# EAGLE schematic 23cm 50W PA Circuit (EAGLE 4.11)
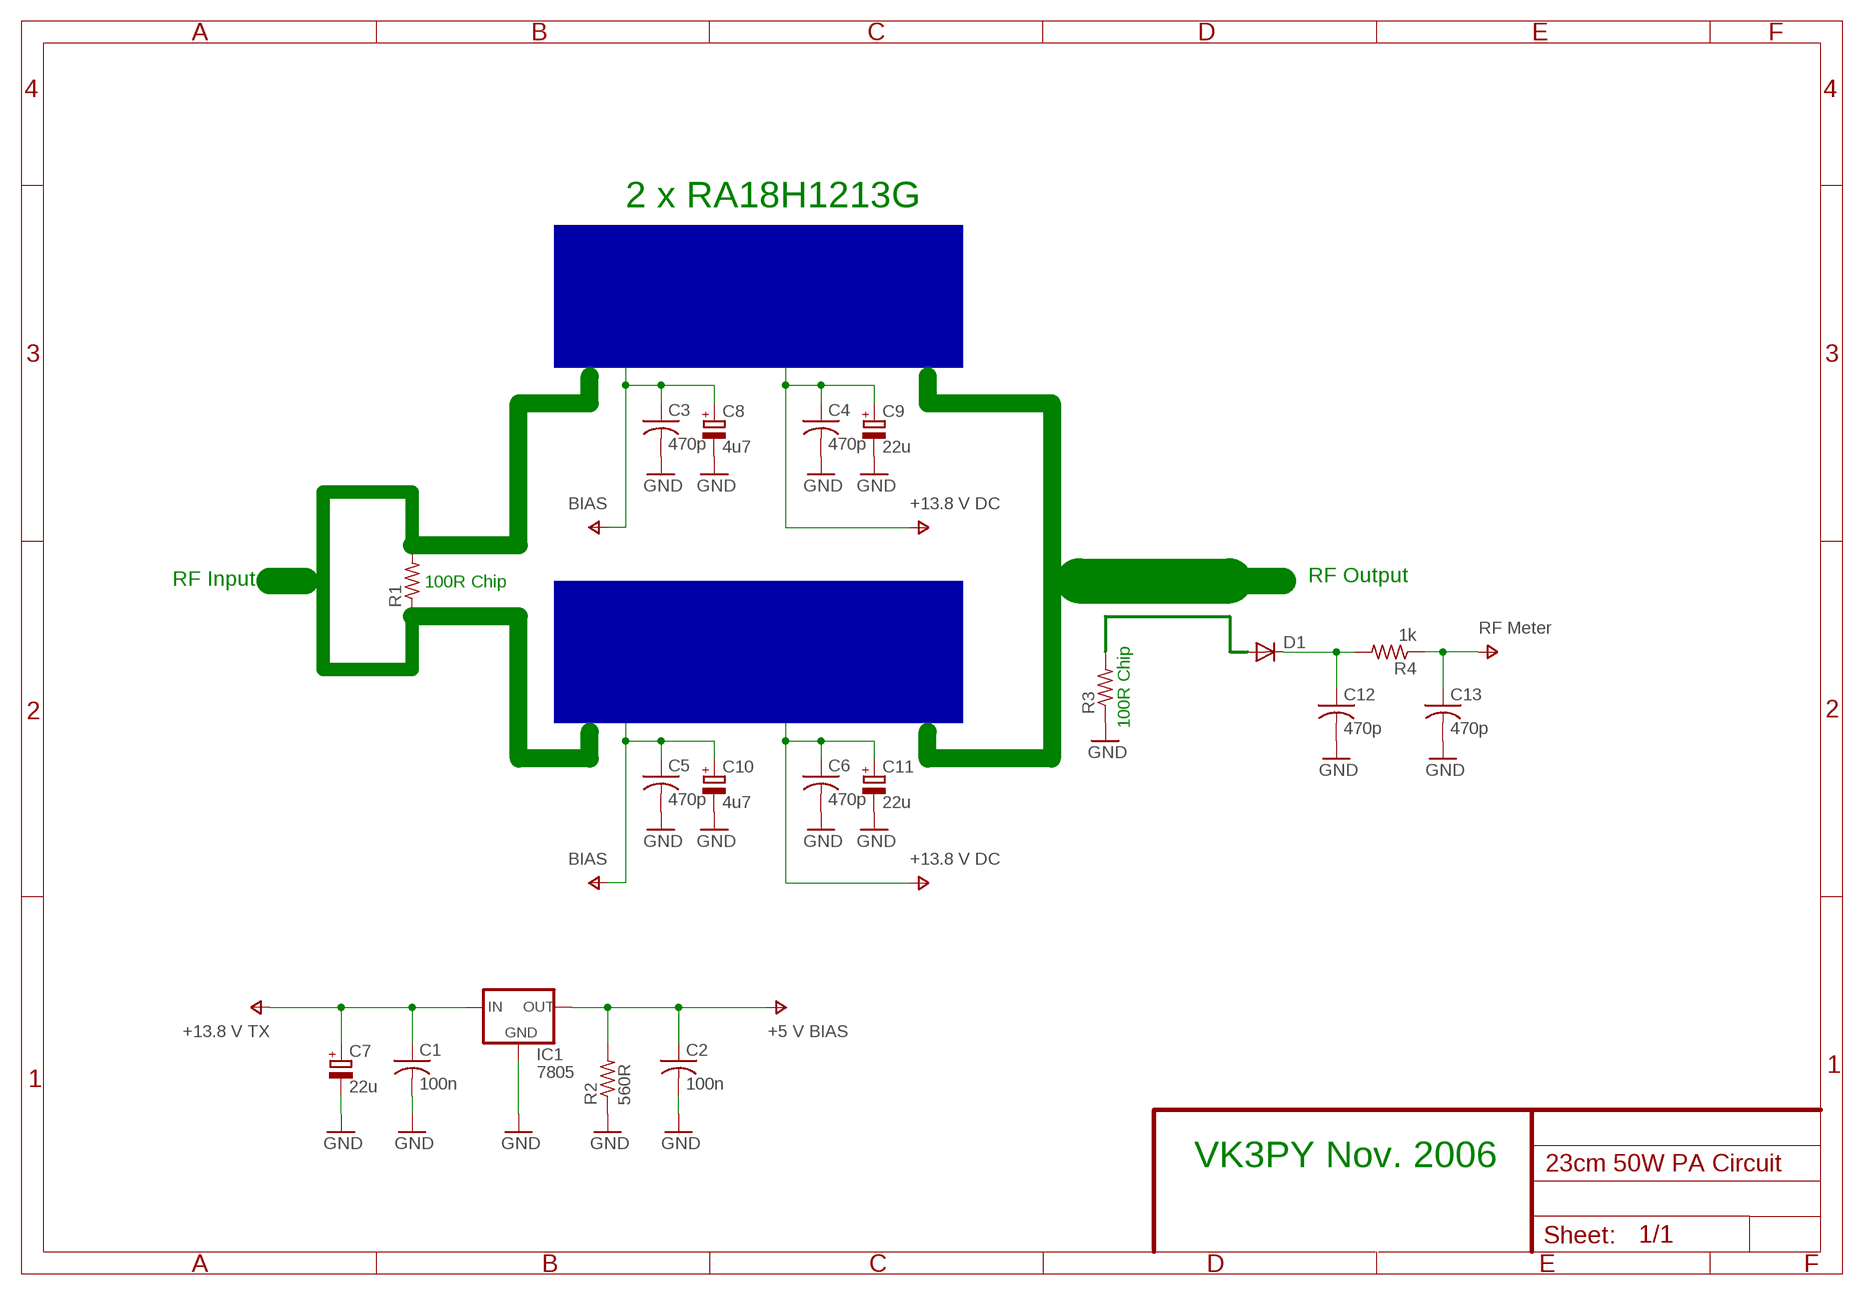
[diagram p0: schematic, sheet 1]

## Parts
C1  100n  C-USC1206  [C1206]
C2  100n  C-USC1206  [C1206]
C3  470p  C-USC1206  [C1206]
C4  470p  C-USC1206  [C1206]
C5  470p  C-USC1206  [C1206]
C6  470p  C-USC1206  [C1206]
C7  22u  CPOL-EU153CLV-0605  [153CLV-0605]
C8  4u7  CPOL-EU153CLV-0605  [153CLV-0605]
C9  22u  CPOL-EU153CLV-0605  [153CLV-0605]
C10  4u7  CPOL-EU153CLV-0605  [153CLV-0605]
C11  22u  CPOL-EU153CLV-0605  [153CLV-0605]
C12  470p  C-USC1206  [C1206]
C13  470p  C-USC1206  [C1206]
D1  1N4148  [DO35-10]
IC1  7805  78XXL  [78XXL]
R1  R-US_R1206  [R1206]
R2  560R  R-US_R1206  [R1206]
R3  R-US_R1206  [R1206]
R4  1k  R-US_R1206  [R1206]

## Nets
GND: C1.2 C2.2 C3.2 C4.2 C5.2 C6.2 C7.- C8.- C9.- C10.- C11.- C12.2 C13.2 IC1.GND R2.1 R3.1
N$1: D1.A R3.2
N$2: C12.1 D1.C R4.2
N$57: R1.1 R1.2
V+: C1.1 C2.1 C3.1 C4.1 C5.1 C6.1 C7.+ C8.+ C9.+ C10.+ C11.+ C13.1 IC1.IN IC1.OUT R2.2 R4.1 ; supply symbol labelled +13.8 V DC, BIAS, +5 V BIAS, +13.8 V TX, RF Meter

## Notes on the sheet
- 2 x RA18H1213G
- RF In | Bias | +DC | RF Out
- RF Input | RF Output
- 100R Chip
- RF In | Bias | +DC | RF Out
- 100R Chip
- VK3PY Nov. 2006

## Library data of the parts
C1-C6 C12 C13 = rcl:C-US: CAPACITOR, American symbol
C7-C11 = rcl:CPOL-EU: POLARIZED CAPACITOR, European symbol
D1 = diode:1N4148: DIODE
IC1 = v-reg:78XXL: VOLTAGE REGULATOR
R1-R4 = rcl:R-US_: RESISTOR, American symbol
